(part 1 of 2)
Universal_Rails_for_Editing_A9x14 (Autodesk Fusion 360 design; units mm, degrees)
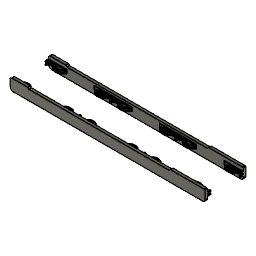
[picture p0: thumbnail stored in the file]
parameter "d466" = -2.1
extrude "Extrude1" new body blind 15
extrude "Extrude2" add blind 2
extrude "Extrude3" cut blind -100
extrude "Extrude4" cut blind -18
extrude "Extrude5" add of existing geometry blind 20
extrude "Extrude6" add of existing geometry blind 20
extrude "Extrude7" cut blind -30
extrude "Extrude8" cut of existing geometry blind -2.5
extrude "Extrude9" cut of existing geometry blind -2.5
extrude "Extrude10" cut of existing geometry blind -28
extrude "Extrude11" add of existing geometry blind 2
extrude "Extrude12" cut blind -21
extrude "Extrude13" cut blind -130
extrude "Extrude14" cut blind -14
extrude "Extrude15" cut blind -4
extrude "Extrude16" cut blind -9
extrude "Extrude17" cut blind -115
extrude "Extrude18" new body blind -2.75
extrude "Extrude19" new body blind -2.75
extrude "Extrude20" cut blind -2
extrude "Extrude21" new body blind -2
extrude "Extrude22" add of existing geometry blind 0.75
extrude "Extrude23" cut blind -9
extrude "Extrude24" cut blind -65
extrude "Extrude25" new body blind 1.5
extrude "Extrude26" cut blind -68
chamfer "Chamfer1" distance 1.5
chamfer "Chamfer2" distance 1.5
extrude "Extrude27" cut blind -0.5
extrude "Extrude28" add blind 1
chamfer "Chamfer3" distance 1
extrude "Extrude29" add of existing geometry blind 1
chamfer "Chamfer4" distance 1
extrude "Extrude30" cut of existing geometry blind -8
extrude "Extrude31" cut blind -2.75
extrude "Extrude32" cut blind -2.75
extrude "Extrude33" cut blind -2.75
extrude "Extrude34" cut blind -2.75
chamfer "Chamfer5" distance 3
chamfer "Chamfer6" distance 1
chamfer "Chamfer7" distance 1
chamfer "Chamfer8" distance 1
extrude "Extrude35" cut blind -0.1
extrude "Extrude36" cut blind -0.1
sketch "Sketch27" plane through (0, -1, 0) normal (0, -1, 0) x axis (1, 0, 0)
  line L1 (3, -2) -> (3, 15)
  line L2 (276.5, -2) -> (3, -2)
  line L3 (276.5, 15) -> (276.5, -2)
  line L4 (3, 15) -> (276.5, 15)
  line L5 (24, -1) -> (126, -1)
  line L6 (24, 14) -> (24, -1)
  line L7 (118, 14) -> (24, 14)
  line L8 (126, -1) -> (118, 14)
  line L9 (153, 10) -> (153, 15)
  line L10 (157.6985, 11.7101) -> (153, 10)
  line L11 (158, 10) -> (153, 10)
  line L12 (157.6985, 3.7101) -> (157.6985, 11.7101)
  line L13 (153, 5.4202) -> (157.6985, 3.7101)
  line L14 (162.6985, 3.7101) -> (157.6985, 3.7101)
  line L15 (153, -2) -> (153, 5.4202)
  circle C1 centre (198.75, 8) radius 1.25
  circle C2 centre (12, 8) radius 1.25
  point P12 (153, 15)
  point P19 (153, -2)
  point P13 (153, 10)
  point P14 (157.6985, 11.7101)
  point P16 (157.6985, 3.7101)
  point P17 (153, 5.4202)
  coincident L4 P12
  perpendicular L4 L9
  horizontal L11
  perpendicular L4 L12
  horizontal L14
  coincident L2 P19
  perpendicular L2 L15
  dimension "d170" distance P13 P14 = 5
  dimension "d171" angle L10 L11 = 20
  dimension "d172" distance P14 P16 = 8
  dimension "d173" angle L13 L14 = 160
  dimension "d174" distance P16 P17 = 5
sketch "Sketch28" plane through (0, 99, 0) normal (0, 1, 0) x axis (-1, 0, 0)
  line L1 (-3, 15) -> (-3, -2)
  line L2 (-25, 15) -> (-3, 15)
  line L3 (-26.7678, 13.2322) -> (-25, 15)
  line L4 (-226.7678, 13.2322) -> (-26.7678, 13.2322)
  line L5 (-228.5355, 15) -> (-226.7678, 13.2322)
  line L6 (-276.5, 15) -> (-228.5355, 15)
  line L7 (-276.5, 0) -> (-276.5, 15)
  line L8 (-276.5, -2) -> (-276.5, 0)
  line L9 (-3, -2) -> (-276.5, -2)
  line L10 (-126.1773, 9) -> (-126.1773, 13.2322)
  line L11 (-121.4789, 10.7101) -> (-126.1773, 9)
  line L12 (-121.1773, 9) -> (-126.1773, 9)
  line L13 (-121.4789, 2.7101) -> (-121.4789, 10.7101)
  line L14 (-126.1773, 4.4202) -> (-121.4789, 2.7101)
  line L15 (-116.4789, 2.7101) -> (-121.4789, 2.7101)
  line L16 (-126.1773, -2) -> (-126.1773, 4.4202)
  line L17 (-154.3022, -2) -> (-126.1773, -2)
  circle C1 centre (-245.5, 8) radius 1.25
  circle C2 centre (-12, 8) radius 1.25
  circle C3 centre (-138.5, 8) radius 1.25
  point P14 (-126.1773, 13.2322)
  point P21 (-126.1773, -2)
  point P15 (-126.1773, 9)
  point P16 (-121.4789, 10.7101)
  point P18 (-121.4789, 2.7101)
  point P19 (-126.1773, 4.4202)
  coincident L4 P14
  perpendicular L4 L10
  horizontal L12
  perpendicular L12 L13
  horizontal L15
  coincident L9 P21
  perpendicular L9 L16
  horizontal L17
  dimension "d175" angle L11 L12 = 20
  dimension "d176" distance P15 P16 = 5
  dimension "d177" distance P16 P18 = 8
  dimension "d178" angle L14 L15 = 160
  dimension "d179" distance P18 P19 = 5
sketch "Sketch31" plane through (0, 0, -2) normal (0, 0, -1) x axis (1, 0, 0)
  line L1 (172.6093, -76.3093) -> (197.4266, -76.3538)
  line L2 (208.9925, -86.3745) -> (161.1508, -86.2888)
  line L3 (153, -20) -> (153, 1)
  line L4 (126.2, -85) -> (126.2, -99)
  line L5 (153, -20) -> (126.2, -85)
  arc A1 centre (138.75, -49) radius 43.5 clockwise from (172.6093, -76.3093) to (161.1508, -86.2888)
  arc A2 centre (231.25, -49) radius 43.5 clockwise from (208.9925, -86.3745) to (197.4266, -76.3538)
  vertical L3
  vertical L4
copy_paste_bodies "CopyPasteBodies3"
move "Move3"
copy_paste_bodies "CopyPasteBodies4"
move "Move4"
extrude "Extrude38" cut sketch "Sketch27" profile of L2 L3 L4 C1 L9 L10 L12 L13 L15 against normal blind 60
extrude "Extrude39" cut of existing geometry blind -45
extrude "Extrude40" cut sketch "Sketch28" profile of L4 L5 L6 L7 L8 L9 C1 C3 L10 L11 L13 L14 L16 L17 against normal blind 50
extrude "Extrude41" cut of existing geometry blind -30
sketch "Sketch32" plane through (279, 0, 0) normal (1, 0, 0) x axis (0, 1, 0)
  line L1 (2.75, 15) -> (2.75, 0)
  line L2 (1.5, 15) -> (2.75, 15)
  line L3 (1.5, -1.9) -> (1.5, 15)
  line L4 (11.5, -1.9) -> (1.5, -1.9)
  line L5 (11.5, -2) -> (11.5, -1.9)
  line L6 (21.5, -2) -> (11.5, -2)
  line L7 (21.5, -1.9) -> (21.5, -2)
  line L8 (31.5, -1.9) -> (21.5, -1.9)
  line L9 (31.5, -2) -> (31.5, -1.9)
  line L10 (41.5001, -2) -> (31.5, -2)
  line L11 (41.5001, -1.9) -> (41.5001, -2)
  line L12 (56.4999, -1.9) -> (41.5001, -1.9)
  line L13 (56.4999, -2) -> (56.4999, -1.9)
  line L14 (66.5, -2) -> (56.4999, -2)
  line L15 (66.5, -1.9) -> (66.5, -2)
  line L16 (76.5, -1.9) -> (66.5, -1.9)
  line L17 (76.5, -2) -> (76.5, -1.9)
  line L18 (86.5, -2) -> (76.5, -2)
  line L19 (86.5, -1.9) -> (86.5, -2)
  line L20 (95.25, -1.9) -> (86.5, -1.9)
  line L21 (95.25, 0) -> (95.25, -1.9)
  line L22 (2.75, 0) -> (95.25, 0)
  line L23 (-12, -11) -> (105, -11)
  line L24 (-12, 30) -> (-12, -11)
  line L25 (105, 30) -> (-12, 30)
  line L26 (105, -11) -> (105, 30)
  horizontal L23
  vertical L24
  horizontal L25
  vertical L26
extrude "Extrude42" cut sketch "Sketch32" against normal blind 16
extrude "Extrude43" cut of existing geometry blind -10
extrude "Extrude44" cut sketch "Sketch27" profile of L1 L2 L4 C2 L5 L6 L7 L8 L9 L10 L12 L13 L15 against normal blind 45
extrude "Extrude45" cut sketch "Sketch28" profile of L1 L2 L3 L4 L9 C2 L10 L11 L13 L14 L16 against normal blind 51
extrude "Extrude46" cut of existing geometry blind -35
extrude "Extrude47" cut of existing geometry blind -20
extrude "Extrude48" cut of existing geometry blind -35
extrude "Extrude50" cut of existing geometry blind -15
extrude "Extrude51" cut of existing geometry blind -25
extrude "Extrude52" cut of existing geometry blind -0.3
extrude "Extrude53" cut of existing geometry blind -45
extrude "Extrude54" cut of existing geometry blind 29
extrude "Extrude55" cut of existing geometry blind -0.4
extrude "Extrude56" cut of existing geometry blind -2
extrude "Extrude57" cut of existing geometry blind -2
extrude "Extrude58" cut of existing geometry blind -2
extrude "Extrude77" add of existing geometry blind 0.5
extrude "Extrude78" add of existing geometry blind 0.5
fillet "Fillet21" radius 5.5
fillet "Fillet22" radius 1.75
extrude "Extrude79" add of existing geometry blind 0.1
extrude "Extrude80" add of existing geometry blind 0.1
extrude "Extrude81" add of existing geometry blind 0.1
extrude "Extrude82" add of existing geometry blind 0.1
extrude "Extrude83" cut of existing geometry blind -25
delete_face "DeleteFace1"
delete_face "DeleteFace2"
delete_face "DeleteFace3"
delete_face "DeleteFace4"
delete_face "DeleteFace5"
delete_face "DeleteFace6"
delete_face "DeleteFace7"
delete_face "DeleteFace8"
sketch "Sketch35" plane through (0, 97.25, 0) normal (0, -1, 0) x axis (1, 0, 0)
  line L1 (26.7678, 13.2322) -> (132.5, 13.2322)
  line L2 (25, 15) -> (26.7678, 13.2322)
  line L3 (18, 15) -> (25, 15)
  line L4 (18, 0) -> (18, 15)
  line L5 (132.5, 0) -> (18, 0)
  line L6 (132.5, 13.2322) -> (132.5, 0)
extrude "Extrude84" add of existing geometry blind 2.2
extrude "Extrude85" cut of existing geometry blind -2.2
extrude "Extrude86" add of existing geometry blind 108
delete_face "DeleteFace9"
delete_face "DeleteFace10"
delete_face "DeleteFace11"
delete_face "DeleteFace12"
delete_face "DeleteFace13"
delete_face "DeleteFace14"
delete_face "DeleteFace15"
delete_face "DeleteFace16"
delete_face "DeleteFace17"
delete_face "DeleteFace18"
delete_face "DeleteFace19"
copy_paste_bodies "CopyPasteBodies5"
move "Move7"
extrude "Extrude87" add of existing geometry blind 0.3
sketch "Sketch36" plane through (0, -1, 0) normal (0, -1, 0) x axis (1, 0, 0)
  line L1 (0, 15) -> (279, 15)
  line L2 (0, -2) -> (0, 15)
  line L3 (279, -2) -> (0, -2)
  line L4 (279, 15) -> (279, -2)
  line L5 (0, 15) -> (279, 15)
  line L6 (0, 10.3) -> (279, 10.3)
  circle C1 centre (198.75, 8) radius 1.25
  circle C2 centre (12, 8) radius 1.25
  point P2 (279, 15)
  point P8 (279, 15)
  point P3 (0, 15)
  point P9 (0, 15)
  coincident P2 P8
  coincident P3 P9
  dimension "d330" = -4.7
move "Move9"
move "Move10"
move "Move11"
copy_paste_bodies "CopyPasteBodies6"
move "Move12"
move "Move13"
extrude "Extrude88" cut of existing geometry blind 12 bodies "(1) (1) (1) (1)", "(1) (1) (1) (2)"
extrude "Extrude89" cut of existing geometry blind -8.5
extrude "Extrude90" cut of existing geometry blind -1
fillet "Fillet23" radius 0.2
fillet "Fillet24" radius 0.05
fillet "Fillet25" radius 0.05
move "Move14"
copy_paste_bodies "CopyPasteBodies7"
move "Move15"
move "Move16"
copy_paste_bodies "CopyPasteBodies8"
move "Move17"
copy_paste_bodies "CopyPasteBodies9"
move "Move18"
move "Move19"
move "Move20"
move "Move21"
move "Move22"
extrude "Extrude91" add sketch "Sketch35" along normal blind 1.95 bodies "(1) (1) (2)", "(1) (1) (1)"
extrude "Extrude92" add of existing geometry blind 1.95
copy_paste_bodies "CopyPasteBodies10"
move "Move23"
move "Move24"
move "Move25"
extrude "Extrude93" cut of existing geometry blind 8 bodies "(1) (1) (1) (3) (1) (1) (1)"
extrude "Extrude94" cut of existing geometry blind -2
sketch "Sketch37" plane through (0, 0, -2) normal (0, 0, -1) x axis (1, 0, 0)
  line L1 (252, -95.25) -> (277.5, -95.25)
  line L2 (252, -95.25) -> (252, -95.25)
  line L3 (277.5, -95.25) -> (252, -95.25)
  line L4 (252, -98) -> (260, -98)
  line L5 (252, -98) -> (252, -98)
  line L6 (260, -98) -> (252, -98)
  line L7 (0, 1) -> (279, 1)
  line L8 (0, -101.7) -> (0, 1)
  line L9 (279, -101.7) -> (0, -101.7)
  line L10 (279, 1) -> (279, -101.7)
  line L11 (279, -113.4909) -> (334.0073, -113.4909)
  line L12 (279, 5) -> (279, -113.4909)
  line L13 (334.0073, 5) -> (279, 5)
  line L14 (334.0073, -113.4909) -> (334.0073, 5)
  circle C1 centre (190.0257, -90.2243) radius 2
  circle C2 centre (190.0257, -7.7757) radius 2
  circle C3 centre (4.9009, -90.0991) radius 2
  circle C4 centre (97.5257, -90.2243) radius 2
  circle C5 centre (87.4743, -7.7757) radius 2
  circle C6 centre (46.25, -49) radius 43.5
  circle C7 centre (272.4743, -90.2243) radius 3
  circle C8 centre (138.75, -49) radius 43.5
  circle C9 centre (231.25, -49) radius 43.5
  circle C10 centre (97.5257, -7.7757) radius 2
  circle C11 centre (87.4743, -90.2243) radius 2
  circle C12 centre (5.0257, -7.7757) radius 2
  circle C13 centre (272.4743, -7.7757) radius 2
  circle C14 centre (179.9743, -7.7757) radius 2
  circle C15 centre (179.9743, -90.2243) radius 2
  horizontal L11
  vertical L12
  horizontal L13
  vertical L14
extrude "Extrude95" cut sketch "Sketch37" profile of L10 L11 L12 L13 L14 against normal blind 25
copy_paste_bodies "CopyPasteBodies11"
move "Move26"
move "Move27"
move "Move28"
move "Move29"
move "Move30"
sketch "Sketch38" plane through (0, 0, -2) normal (0, 0, -1) x axis (1, 0, 0)
  line L1 (252, -95.25) -> (277.5, -95.25)
  line L2 (252, -95.25) -> (252, -95.25)
  line L3 (277.5, -95.25) -> (252, -95.25)
  line L4 (252, -98) -> (260, -98)
  line L5 (252, -98) -> (252, -98)
  line L6 (260, -98) -> (252, -98)
  line L7 (0, 1) -> (279, 1)
  line L8 (0, -101.7) -> (0, 1)
  line L9 (279, -101.7) -> (0, -101.7)
  line L10 (279, 1) -> (279, -101.7)
  line L11 (0, -117.1495) -> (-75.3849, -117.1495)
  line L12 (0, 1) -> (0, -117.1495)
  line L13 (-75.3849, 1) -> (0, 1)
  line L14 (-75.3849, -117.1495) -> (-75.3849, 1)
  circle C1 centre (190.0257, -90.2243) radius 2
  circle C2 centre (190.0257, -7.7757) radius 2
  circle C3 centre (4.9009, -90.0991) radius 2
  circle C4 centre (97.5257, -90.2243) radius 2
  circle C5 centre (87.4743, -7.7757) radius 2
  circle C6 centre (46.25, -49) radius 43.5
  circle C7 centre (272.4743, -90.2243) radius 3
  circle C8 centre (138.75, -49) radius 43.5
  circle C9 centre (231.25, -49) radius 43.5
  circle C10 centre (97.5257, -7.7757) radius 2
  circle C11 centre (87.4743, -90.2243) radius 2
  circle C12 centre (5.0257, -7.7757) radius 2
  circle C13 centre (272.4743, -7.7757) radius 2
  circle C14 centre (179.9743, -7.7757) radius 2
  circle C15 centre (179.9743, -90.2243) radius 2
  point P19 (0, 1)
  point P30 (0, 1)
  horizontal L11
  vertical L12
  horizontal L13
  vertical L14
  coincident P19 P30
extrude "Extrude96" cut sketch "Sketch38" profile of L8 L11 L12 L13 L14 against normal blind 60
extrude "Extrude97" cut of existing geometry blind 11 bodies "(1) (1) (1) (3) (3)", "(1) (1) (1) (3) (4)"
extrude "Extrude98" cut of existing geometry blind -8.5
extrude "Extrude99" cut of existing geometry blind -1.5
extrude "Extrude100" cut of existing geometry blind 15 bodies "(1) (1) (1) (3) (2) (1)", "Side 1"
extrude "Extrude101" cut of existing geometry blind -8.5
extrude "Extrude102" cut of existing geometry blind -50 bodies "Part 1 (1)"
sketch "Sketch39" plane through (0, 0, 15) normal (0, 0, 1) x axis (-1, 0, 0)
  line L1 (-279, 1) -> (0, 1)
  line L2 (-279, -3.05) -> (-279, 1)
  line L3 (-204.75, -3.05) -> (-279, -3.05)
  line L4 (-204.75, 0) -> (-204.75, -3.05)
  line L5 (-192.75, 0) -> (-204.75, 0)
  line L6 (-192.75, -3.05) -> (-192.75, 0)
  line L7 (-18, -3.05) -> (-192.75, -3.05)
  line L8 (-18, 0) -> (-18, -3.05)
  line L9 (-6, 0) -> (-18, 0)
  line L10 (-6, -3.05) -> (-6, 0)
  line L11 (0, -3.05) -> (-6, -3.05)
  line L12 (0, 1) -> (0, -3.05)
  line L13 (-278.8, -3.05) -> (-279, -3.05)
  line L14 (-279, -3.05) -> (0, -3.05)
  line L15 (-279, -1.05) -> (0, -1.05)
  line L16 (-278.8, -5.05) -> (-279, -5.05)
  arc A1 centre (-279, -3.05) radius 2 clockwise from (-279, -5.05) to (-279, -1.05)
  point P4 (-279, -3.05)
  point P14 (-279, -3.05)
  point P15 (-278.8, -3.05)
  point P13 (0, -3.05)
  point P16 (0, -3.05)
  coincident P4 P14
  coincident L3 P15
  coincident P13 P16
  dimension "d367" = 2
extrude "Extrude103" cut sketch "Sketch39" profile of L2 L3 L4 L6 L7 L8 L10 L11 L12 L13 L14 L15 against normal blind 3
fillet "Fillet26" radius 1.5
fillet "Fillet27" radius 1.5
extrude "Extrude104" cut of existing geometry blind -1
extrude "Extrude105" cut of existing geometry blind -1
fillet "Fillet28" radius 5
delete_face "DeleteFace20"
delete_face "DeleteFace21"
delete_face "DeleteFace22"
extrude "Extrude106" cut of existing geometry blind -1
extrude "Extrude107" cut of existing geometry blind -1
fillet "Fillet29" radius 1.25
fillet "Fillet30" radius 2
fillet "Fillet31" radius 2.5
combine "Combine1" bodies "Part 1 (1)"
combine "Combine2" bodies "(1) (1) (1) (3) (1) (1) (1) (1)", "(1) (1) (1) (3) (2) (1)"
combine "Combine3" bodies "(1) (1) (1) (3) (1) (1) (1) (1)", "(1) (1) (1) (3) (1) (1) (1)"
combine "Combine4" bodies "(1) (1) (1) (3) (4) (1)", "(1) (1) (1) (3) (4) (2)", "(1) (1) (1) (3) (4) (3)", "(1) (1) (1) (3) (4) (4)", "(1) (1) (1) (3) (4) (5)", "(1) (1) (1) (3) (3)", "(1) (1) (1) (3) (1)", "(1) (1) (1) (3)"
combine "Combine5" bodies "(1) (1) (1) (3) (4) (3)", "(1) (1) (1) (3) (4) (5)", "(1) (1) (1) (3) (4) (1)", "(1) (1) (1) (3) (4) (4)"
extrude "Extrude108" add of existing geometry blind 2.5 bodies "(1) (1) (1) (3) (4)", "(1) (1) (1) (3) (2)"
extrude "Extrude109" add of existing geometry blind 2.5
extrude "Extrude110" add of existing geometry blind 2.5
extrude "Extrude111" add of existing geometry blind 2.5
extrude "Extrude112" cut of existing geometry blind -2.5
delete_face "DeleteFace23"
delete_face "DeleteFace24"
delete_face "DeleteFace25"
extrude "Extrude113" cut of existing geometry blind -2.5
extrude "Extrude114" cut of existing geometry blind -3
extrude "Extrude115" cut of existing geometry blind -3
extrude "Extrude116" cut of existing geometry blind -0.5
extrude "Extrude117" cut of existing geometry blind -0.5
fillet "Fillet32" radius 2
extrude "Extrude118" add of existing geometry blind 2
fillet "Fillet33" radius 2
sketch "Sketch40" plane through (0, -2.5, 0) normal (0, 1, 0) x axis (-1, 0, 0)
  line L1 (-192.75, -1) -> (-204.75, -1)
  line L2 (-192.75, 15) -> (-192.75, -1)
  line L3 (-204.75, 15) -> (-192.75, 15)
  line L4 (-204.75, -1) -> (-204.75, 15)
  line L5 (-192.75, -1) -> (-204.75, -1)
  line L6 (-192.75, 0) -> (-204.75, 0)
  circle C1 centre (-198.75, 8) radius 1.25
  point P2 (-204.75, -1)
  point P7 (-204.75, -1)
  point P3 (-192.75, -1)
  point P8 (-192.75, -1)
  coincident P2 P7
  coincident P3 P8
  dimension "d416" distance ORIGIN L5 = -1
extrude "Extrude119" new body sketch "Sketch40" profile of L1 L2 L4 L5 L6 along normal blind 5.55
sketch "Sketch41" plane through (0, -2.5, 0) normal (0, 1, 0) x axis (-1, 0, 0)
  line L1 (-6, -1) -> (-18, -1)
  line L2 (-6, 15) -> (-6, -1)
  line L3 (-18, 15) -> (-6, 15)
  line L4 (-18, -1) -> (-18, 15)
  line L5 (-6, -1) -> (-18, -1)
  line L6 (-6, 0) -> (-18, 0)
  circle C1 centre (-12, 8) radius 1.25
  point P2 (-18, -1)
  point P7 (-18, -1)
  point P3 (-6, -1)
  point P8 (-6, -1)
  coincident P2 P7
  coincident P3 P8
  dimension "d419" distance ORIGIN L5 = -1
extrude "Extrude120" new body sketch "Sketch41" profile of L1 L2 L4 L5 L6 along normal blind 5.55
combine "Combine6" bodies "(1) (1) (1) (3) (4) (2)"
base_mesh_feature "Base Mesh Feature3"
modify "Modify1"
modify "Modify2"
modify "Modify3"
modify "Modify4"
convert_mesh "Convert Mesh" bodies "(1)"
combine "Combine7" bodies "Side 1"
extrude "Extrude121" add of existing geometry blind 1
extrude "Extrude122" add of existing geometry blind 1
fillet "Fillet34" radius 1.5
fillet "Fillet35" radius 1.5
sketch "Sketch42" plane through (0, 97.7, 0) normal (0, -1, 0) x axis (1, 0, 0)
  line L1 (251.5, -1) -> (239.5, -1)
  line L2 (251.5, 15) -> (251.5, -1)
  line L3 (239.5, 15) -> (251.5, 15)
  line L4 (239.5, -1) -> (239.5, 15)
  line L5 (18, -1) -> (6, -1)
  line L6 (132.5, -1) -> (18, -1)
  line L7 (144.5, -1) -> (132.5, -1)
  line L8 (18, 0) -> (6, 0)
  line L9 (132.5, 0) -> (18, 0)
  line L10 (144.5, 0) -> (132.5, 0)
  line L11 (18, -1) -> (18, 0)
  line L12 (144.5, 0) -> (144.5, -1)
  line L13 (132.5, -1) -> (132.5, 0)
  line L14 (6, -0.1) -> (6, 0)
  line L15 (6, -1) -> (6, -0.1)
  circle C1 centre (245.5, 8) radius 1.25
  horizontal L5
  parallel L5 L6
  parallel L6 L7
  perpendicular L6 L11
  perpendicular L10 L12
  perpendicular L6 L13
  perpendicular L8 L14
  perpendicular L5 L15
  dimension "d430" distance ORIGIN L7 = -1
extrude "Extrude123" new body sketch "Sketch42" profile of L5 L7 L8 L10 L11 L12 L13 L14 L15 along normal blind 2.4
combine "Combine8" bodies "(1)"
extrude "Extrude124" add of existing geometry blind 1
fillet "Fillet36" radius 1.5
fillet "Fillet37" radius 1.5
sketch "Sketch43" plane through (0, 97.7, 0) normal (0, -1, 0) x axis (1, 0, 0)
  line L1 (251.5, -1) -> (239.5, -1)
  line L2 (251.5, 15) -> (251.5, -1)
  line L3 (239.5, 15) -> (251.5, 15)
  line L4 (239.5, -1) -> (239.5, 15)
  line L5 (239.5, -1) -> (251.5, -1)
  line L6 (239.5, 1.5) -> (251.5, 1.5)
  circle C1 centre (245.5, 8) radius 1.25
  point P3 (251.5, -1)
  point P7 (251.5, -1)
  point P2 (239.5, -1)
  point P8 (239.5, -1)
  coincident P3 P7
  coincident P2 P8
  dimension "d439" = 2.5
extrude "Extrude125" new body sketch "Sketch43" profile of L1 L2 L4 L5 L6 along normal blind 2.45
combine "Combine9"
fillet "Fillet38" radius 1.5
extrude "Extrude126" cut of existing geometry blind -0.05
extrude "Extrude127" add of existing geometry blind 0.5
chamfer "Chamfer9" distance 0.5
chamfer "Chamfer10" distance 0.5
chamfer "Chamfer11" distance 0.5
chamfer "Chamfer12" distance 0.5
fillet "Fillet39" radius 0.5
fillet "Fillet40" radius 0.5
fillet "Fillet41" radius 0.25
delete_face "DeleteFace26"
extrude "Extrude128" cut of existing geometry blind -43
fillet "Fillet42" radius 1.5
delete_face "DeleteFace27"
extrude "Extrude129" cut of existing geometry blind -0.55
extrude "Extrude130" cut of existing geometry blind -0.2
extrude "Extrude131" cut of existing geometry no distance stored
fillet "Fillet43" radius 1
sketch "Sketch44" plane through (0, -4, 0) normal (0, -1, 0) x axis (1, 0, 0)
  line L1 (2, 15) -> (203.25, 15)
  line L2 (0, 4) -> (0, 13)
  line L3 (274, -1) -> (5, -1)
  line L4 (279, 10.5) -> (279, 4)
  line L5 (206.25, 10.5) -> (279, 10.5)
  line L6 (204.75, 13.5) -> (204.75, 12)
  line L7 (12, 9) -> (12, 8)
  arc A1 centre (203.25, 13.5) radius 1.5 clockwise from (203.25, 15) to (204.75, 13.5)
  arc A2 centre (2, 13) radius 2 clockwise from (0, 13) to (2, 15)
  arc A3 centre (5, 4) radius 5 clockwise from (5, -1) to (0, 4)
  arc A4 centre (274, 4) radius 5 clockwise from (279, 4) to (274, -1)
  arc A5 centre (206.25, 12) radius 1.5 clockwise from (206.25, 10.5) to (204.75, 12)
  circle C1 centre (198.75, 8) radius 1.75
  circle C2 centre (12, 8) radius 1.75
  circle C3 centre (12, 9) radius 1
  point P19 (12, 8)
  point P20 (12, 8)
  point P21 (12, 9)
  point P22 (12, 9)
  coincident P19 P20
  vertical L7
  coincident P21 P22
  dimension "d471" distance P20 P21 = 1
  dimension "d472" diameter C3 = 2
extrude "Extrude132" new body sketch "Sketch44" profile of C2 C3 along normal blind 1
delete_face "DeleteFace28"
delete_face "DeleteFace29"
extrude "Extrude133" cut of existing geometry blind -18
chamfer "Chamfer13" distance 0.75
sketch "Sketch45" plane through (0, -4, 0) normal (0, -1, 0) x axis (1, 0, 0)
  line L1 (2, 15) -> (203.25, 15)
  line L2 (0, 4) -> (0, 13)
  line L3 (274, -1) -> (5, -1)
  line L4 (279, 10.5) -> (279, 4)
  line L5 (206.25, 10.5) -> (279, 10.5)
  line L6 (204.75, 13.5) -> (204.75, 12)
  line L7 (198.75, 9) -> (198.75, 8)
  arc A1 centre (203.25, 13.5) radius 1.5 clockwise from (203.25, 15) to (204.75, 13.5)
  arc A2 centre (2, 13) radius 2 clockwise from (0, 13) to (2, 15)
  arc A3 centre (5, 4) radius 5 clockwise from (5, -1) to (0, 4)
  arc A4 centre (274, 4) radius 5 clockwise from (279, 4) to (274, -1)
  arc A5 centre (206.25, 12) radius 1.5 clockwise from (206.25, 10.5) to (204.75, 12)
  circle C1 centre (198.75, 8) radius 1.75
  circle C2 centre (12, 9) radius 1.75
  circle C3 centre (198.75, 8) radius 1
  circle C4 centre (198.75, 9) radius 1
  point P20 (198.75, 8)
  point P21 (198.75, 8)
  point P22 (198.75, 9)
  point P23 (198.75, 9)
  concentric C1 C3
  coincident P20 P21
  coincident C3 P22
  vertical L7
  coincident P22 P23
  dimension "d478" diameter C3 = 2
  dimension "d479" diameter C4 = 2
extrude "Extrude134" add sketch "Sketch45" profile of C1 C3 L7 C4 along normal blind 2.4
delete_face "DeleteFace30"
delete_face "DeleteFace31"
extrude "Extrude135" cut of existing geometry blind -14
chamfer "Chamfer14" distance 0.75
sketch "Sketch46" plane through (0, 3.05, 0) normal (0, 1, 0) x axis (-1, 0, 0)
  line L1 (-158.6084, 10) -> (-118.9527, 10)
  line L2 (-158.6088, 8.7626) -> (-158.6084, 10)
  line L3 (-158.6088, 8.5) -> (-158.6088, 8.7626)
  line L4 (-158.9877, 8.5) -> (-158.6088, 8.5)
  line L5 (-159.0663, 8.5) -> (-158.9877, 8.5)
  line L6 (-185.3992, 8.5) -> (-159.0663, 8.5)
  line L7 (-185.4405, 8.5) -> (-185.3992, 8.5)
  line L8 (-185.4826, 8.5) -> (-185.4405, 8.5)
  line L9 (-185.506, 8.5) -> (-185.4826, 8.5)
  line L10 (-185.5175, 8.5) -> (-185.506, 8.5)
  line L11 (-185.5304, 8.5) -> (-185.5175, 8.5)
  line L12 (-185.5304, 8.5056) -> (-185.5304, 8.5)
  line L13 (-185.5304, 10) -> (-185.5304, 8.5056)
  line L14 (-185.5307, 10) -> (-185.5304, 10)
  line L15 (-185.5307, 8.5056) -> (-185.5307, 10)
  line L16 (-185.5307, 8.5) -> (-185.5307, 8.5056)
  line L17 (-185.5342, 8.5) -> (-185.5307, 8.5)
  line L18 (-185.5382, 8.5) -> (-185.5342, 8.5)
  line L19 (-185.547, 8.5) -> (-185.5382, 8.5)
  line L20 (-185.5661, 8.5) -> (-185.547, 8.5)
  line L21 (-185.6018, 8.5) -> (-185.5661, 8.5)
  line L22 (-185.6391, 8.5) -> (-185.6018, 8.5)
  line L23 (-192.75, 8.5) -> (-185.6391, 8.5)
  line L24 (-192.75, 6.5) -> (-192.75, 8.5)
  line L25 (-185.6391, 6.5) -> (-192.75, 6.5)
  line L26 (-185.6018, 6.5) -> (-185.6391, 6.5)
  line L27 (-185.5661, 6.5) -> (-185.6018, 6.5)
  line L28 (-185.547, 6.5) -> (-185.5661, 6.5)
  line L29 (-185.5382, 6.5) -> (-185.547, 6.5)
  line L30 (-185.5342, 6.5) -> (-185.5382, 6.5)
  line L31 (-185.5324, 6.5) -> (-185.5342, 6.5)
  line L32 (-185.5323, 6.5) -> (-185.5324, 6.5)
  line L33 (-185.5321, 6.5) -> (-185.5323, 6.5)
  line L34 (-185.5318, 6.5) -> (-185.5321, 6.5)
  line L35 (-185.5316, 6.5) -> (-185.5318, 6.5)
  line L36 (-185.5314, 6.5) -> (-185.5316, 6.5)
  line L37 (-185.5311, 6.5) -> (-185.5314, 6.5)
  line L38 (-185.5307, 6.5) -> (-185.5311, 6.5)
  line L39 (-185.5307, 4.7056) -> (-185.5307, 6.5)
  line L40 (-185.5307, 4.7) -> (-185.5307, 4.7056)
  line L41 (-185.5311, 4.7) -> (-185.5307, 4.7)
  line L42 (-185.5743, 4.7) -> (-185.5311, 4.7)
  line L43 (-185.6006, 4.7) -> (-185.5743, 4.7)
  line L44 (-185.6265, 4.7) -> (-185.6006, 4.7)
  line L45 (-185.6513, 4.7) -> (-185.6265, 4.7)
  line L46 (-185.6745, 4.7) -> (-185.6513, 4.7)
  line L47 (-185.6956, 4.7) -> (-185.6745, 4.7)
  line L48 (-185.8704, 4.7) -> (-185.6956, 4.7)
  line L49 (-186.1657, 4.7) -> (-185.8704, 4.7)
  line L50 (-186.6749, 4.7) -> (-186.1657, 4.7)
  line L51 (-187.4335, 4.7) -> (-186.6749, 4.7)
  line L52 (-188.3776, 4.7) -> (-187.4335, 4.7)
  line L53 (-189.2796, 4.7) -> (-188.3776, 4.7)
  line L54 (-192.75, 4.7) -> (-189.2796, 4.7)
  line L55 (-192.75, 2.5) -> (-192.75, 4.7)
  line L56 (-203.25, 1) -> (-194.25, 1)
  line L57 (-204.75, 4.7) -> (-204.75, 2.5)
  line L58 (-207.5504, 4.7) -> (-204.75, 4.7)
  line L59 (-208.7719, 4.7) -> (-207.5504, 4.7)
  line L60 (-209.2062, 4.7) -> (-208.7719, 4.7)
  line L61 (-211.0064, 4.7) -> (-209.2062, 4.7)
  line L62 (-211.4528, 4.7) -> (-211.0064, 4.7)
  line L63 (-211.4523, 6.2374) -> (-211.4528, 4.7)
  line L64 (-211.4524, 6.5) -> (-211.4523, 6.2374)
  line L65 (-211.0734, 6.5) -> (-211.4524, 6.5)
  line L66 (-210.9948, 6.5) -> (-211.0734, 6.5)
  line L67 (-204.75, 6.5) -> (-210.9948, 6.5)
  line L68 (-204.75, 8.5) -> (-204.75, 6.5)
  line L69 (-210.9948, 8.5) -> (-204.75, 8.5)
  line L70 (-211.0734, 8.5) -> (-210.9948, 8.5)
  line L71 (-211.4524, 8.5) -> (-211.0734, 8.5)
  line L72 (-211.4523, 8.7626) -> (-211.4524, 8.5)
  line L73 (-211.4527, 10) -> (-211.4523, 8.7626)
  line L74 (-251.1084, 10) -> (-211.4527, 10)
  line L75 (-251.1088, 8.7626) -> (-251.1084, 10)
  line L76 (-251.1088, 8.5) -> (-251.1088, 8.7626)
  line L77 (-251.4877, 8.5) -> (-251.1088, 8.5)
  line L78 (-251.5663, 8.5) -> (-251.4877, 8.5)
  line L79 (-277.8992, 8.5) -> (-251.5663, 8.5)
  line L80 (-277.9405, 8.5) -> (-277.8992, 8.5)
  line L81 (-277.9826, 8.5) -> (-277.9405, 8.5)
  line L82 (-278.006, 8.5) -> (-277.9826, 8.5)
  line L83 (-278.0175, 8.5) -> (-278.006, 8.5)
  line L84 (-278.0304, 8.5) -> (-278.0175, 8.5)
  line L85 (-278.0304, 8.5056) -> (-278.0304, 8.5)
  line L86 (-278.0304, 10) -> (-278.0304, 8.5056)
  line L87 (-278.0307, 10) -> (-278.0304, 10)
  line L88 (-278.0307, 8.5056) -> (-278.0307, 10)
  line L89 (-278.0307, 8.5) -> (-278.0307, 8.5056)
  line L90 (-278.0342, 8.5) -> (-278.0307, 8.5)
  line L91 (-278.0382, 8.5) -> (-278.0342, 8.5)
  line L92 (-278.047, 8.5) -> (-278.0382, 8.5)
  line L93 (-278.0661, 8.5) -> (-278.047, 8.5)
  line L94 (-278.1018, 8.5) -> (-278.0661, 8.5)
  line L95 (-278.1391, 8.5) -> (-278.1018, 8.5)
  line L96 (-279, 8.5) -> (-278.1391, 8.5)
  line L97 (-279, 6.5) -> (-279, 8.5)
  line L98 (-278.1391, 6.5) -> (-279, 6.5)
  line L99 (-278.1018, 6.5) -> (-278.1391, 6.5)
  line L100 (-278.0661, 6.5) -> (-278.1018, 6.5)
  line L101 (-278.047, 6.5) -> (-278.0661, 6.5)
  line L102 (-278.0382, 6.5) -> (-278.047, 6.5)
  line L103 (-278.0342, 6.5) -> (-278.0382, 6.5)
  line L104 (-278.0324, 6.5) -> (-278.0342, 6.5)
  line L105 (-278.0323, 6.5) -> (-278.0324, 6.5)
  line L106 (-278.0321, 6.5) -> (-278.0323, 6.5)
  line L107 (-278.0318, 6.5) -> (-278.0321, 6.5)
  line L108 (-278.0316, 6.5) -> (-278.0318, 6.5)
  line L109 (-278.0314, 6.5) -> (-278.0316, 6.5)
  line L110 (-278.0311, 6.5) -> (-278.0314, 6.5)
  line L111 (-278.0307, 6.5) -> (-278.0311, 6.5)
  line L112 (-278.0307, 4.7056) -> (-278.0307, 6.5)
  line L113 (-278.0307, 4.7) -> (-278.0307, 4.7056)
  line L114 (-278.0311, 4.7) -> (-278.0307, 4.7)
  line L115 (-278.0743, 4.7) -> (-278.0311, 4.7)
  line L116 (-278.1006, 4.7) -> (-278.0743, 4.7)
  line L117 (-278.1265, 4.7) -> (-278.1006, 4.7)
  line L118 (-278.1513, 4.7) -> (-278.1265, 4.7)
  line L119 (-278.1745, 4.7) -> (-278.1513, 4.7)
  line L120 (-278.1956, 4.7) -> (-278.1745, 4.7)
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  point P385 (-61.3466, 10)
  point P386 (-31.3466, 10)
  point P388 (-61.3466, 4)
  dimension "d485" distance P385 P386 = 30
  dimension "d486" distance P385 P388 = 6
extrude "Extrude136" cut sketch "Sketch46" against normal blind 5.55
extrude "Extrude137" cut of existing geometry blind -6
fillet "Fillet44" radius 3.5
sketch "Sketch47" plane through (0, 3.05, 0) normal (0, 1, 0) x axis (-1, 0, 0)
  line L1 (-185.5175, 6.5) -> (-185.5304, 6.5)
  line L2 (-185.506, 6.5) -> (-185.5175, 6.5)
  line L3 (-185.4826, 6.5) -> (-185.506, 6.5)
  line L4 (-185.4405, 6.5) -> (-185.4826, 6.5)
  line L5 (-185.3992, 6.5) -> (-185.4405, 6.5)
  line L6 (-159.0663, 6.5) -> (-185.3992, 6.5)
  line L7 (-158.9877, 6.5) -> (-159.0663, 6.5)
  line L8 (-158.6088, 6.5) -> (-158.9877, 6.5)
  line L9 (-158.6088, 6.2374) -> (-158.6088, 6.5)
  line L10 (-158.6083, 4.7) -> (-158.6088, 6.2374)
  line L11 (-159.0547, 4.7) -> (-158.6083, 4.7)
  line L12 (-160.8549, 4.7) -> (-159.0547, 4.7)
  line L13 (-161.2892, 4.7) -> (-160.8549, 4.7)
  line L14 (-162.5107, 4.7) -> (-161.2892, 4.7)
  line L15 (-180.9918, 4.7) -> (-162.5107, 4.7)
  line L16 (-185.3987, 4.7) -> (-180.9918, 4.7)
  line L17 (-185.4402, 4.7) -> (-185.3987, 4.7)
  line L18 (-185.4824, 4.7) -> (-185.4402, 4.7)
  line L19 (-185.506, 4.7) -> (-185.4824, 4.7)
  line L20 (-185.5174, 4.7) -> (-185.506, 4.7)
  line L21 (-185.5229, 4.7) -> (-185.5174, 4.7)
  line L22 (-185.5272, 4.7) -> (-185.5229, 4.7)
  line L23 (-185.5304, 4.7) -> (-185.5272, 4.7)
  line L24 (-185.5304, 6.4944) -> (-185.5304, 4.7)
  line L25 (-185.5304, 6.5) -> (-185.5304, 6.4944)
  line L26 (-118.5734, 6.5) -> (-118.9524, 6.5)
  line L27 (-118.4948, 6.5) -> (-118.5734, 6.5)
  line L28 (-93.1391, 6.5) -> (-118.4948, 6.5)
  line L29 (-93.1018, 6.5) -> (-93.1391, 6.5)
  line L30 (-93.0661, 6.5) -> (-93.1018, 6.5)
  line L31 (-93.047, 6.5) -> (-93.0661, 6.5)
  line L32 (-93.0382, 6.5) -> (-93.047, 6.5)
  line L33 (-93.0342, 6.5) -> (-93.0382, 6.5)
  line L34 (-93.0324, 6.5) -> (-93.0342, 6.5)
  line L35 (-93.0323, 6.5) -> (-93.0324, 6.5)
  line L36 (-93.0321, 6.5) -> (-93.0323, 6.5)
  line L37 (-93.0318, 6.5) -> (-93.0321, 6.5)
  line L38 (-93.0316, 6.5) -> (-93.0318, 6.5)
  line L39 (-93.0314, 6.5) -> (-93.0316, 6.5)
  line L40 (-93.0311, 6.5) -> (-93.0314, 6.5)
  line L41 (-93.0307, 6.5) -> (-93.0311, 6.5)
  line L42 (-93.0307, 4.7056) -> (-93.0307, 6.5)
  line L43 (-93.0307, 4.7) -> (-93.0307, 4.7056)
  line L44 (-93.0311, 4.7) -> (-93.0307, 4.7)
  line L45 (-93.0743, 4.7) -> (-93.0311, 4.7)
  line L46 (-93.1006, 4.7) -> (-93.0743, 4.7)
  line L47 (-93.1265, 4.7) -> (-93.1006, 4.7)
  line L48 (-93.1513, 4.7) -> (-93.1265, 4.7)
  line L49 (-93.1745, 4.7) -> (-93.1513, 4.7)
  line L50 (-93.1956, 4.7) -> (-93.1745, 4.7)
  line L51 (-93.3704, 4.7) -> (-93.1956, 4.7)
  line L52 (-93.6657, 4.7) -> (-93.3704, 4.7)
  line L53 (-94.1749, 4.7) -> (-93.6657, 4.7)
  line L54 (-94.9335, 4.7) -> (-94.1749, 4.7)
  line L55 (-95.8776, 4.7) -> (-94.9335, 4.7)
  line L56 (-96.7796, 4.7) -> (-95.8776, 4.7)
  line L57 (-115.0504, 4.7) -> (-96.7796, 4.7)
  line L58 (-116.2719, 4.7) -> (-115.0504, 4.7)
  line L59 (-116.7062, 4.7) -> (-116.2719, 4.7)
  line L60 (-118.5064, 4.7) -> (-116.7062, 4.7)
  line L61 (-118.9528, 4.7) -> (-118.5064, 4.7)
  line L62 (-118.9523, 6.2374) -> (-118.9528, 4.7)
  line L63 (-118.9524, 6.5) -> (-118.9523, 6.2374)
  line L64 (-66.1083, 4.7) -> (-66.1088, 6.2374)
  line L65 (-66.5547, 4.7) -> (-66.1083, 4.7)
  line L66 (-68.3549, 4.7) -> (-66.5547, 4.7)
  line L67 (-68.7892, 4.7) -> (-68.3549, 4.7)
  line L68 (-70.0107, 4.7) -> (-68.7892, 4.7)
  line L69 (-88.4918, 4.7) -> (-70.0107, 4.7)
  line L70 (-92.8987, 4.7) -> (-88.4918, 4.7)
  line L71 (-92.9402, 4.7) -> (-92.8987, 4.7)
  line L72 (-92.9824, 4.7) -> (-92.9402, 4.7)
  line L73 (-93.006, 4.7) -> (-92.9824, 4.7)
  line L74 (-93.0174, 4.7) -> (-93.006, 4.7)
  line L75 (-93.0229, 4.7) -> (-93.0174, 4.7)
  line L76 (-93.0272, 4.7) -> (-93.0229, 4.7)
  line L77 (-93.0304, 4.7) -> (-93.0272, 4.7)
  line L78 (-93.0304, 6.4944) -> (-93.0304, 4.7)
  line L79 (-93.0304, 6.5) -> (-93.0304, 6.4944)
  line L80 (-93.0175, 6.5) -> (-93.0304, 6.5)
  line L81 (-93.006, 6.5) -> (-93.0175, 6.5)
  line L82 (-92.9826, 6.5) -> (-93.006, 6.5)
  line L83 (-92.9405, 6.5) -> (-92.9826, 6.5)
  line L84 (-92.8992, 6.5) -> (-92.9405, 6.5)
  line L85 (-66.5663, 6.5) -> (-92.8992, 6.5)
  line L86 (-66.4877, 6.5) -> (-66.5663, 6.5)
  line L87 (-66.1088, 6.5) -> (-66.4877, 6.5)
  line L88 (-66.1088, 6.2374) -> (-66.1088, 6.5)
  line L89 (-251.1083, 4.7) -> (-251.1088, 6.2374)
  line L90 (-251.5547, 4.7) -> (-251.1083, 4.7)
  line L91 (-253.3549, 4.7) -> (-251.5547, 4.7)
  line L92 (-253.7892, 4.7) -> (-253.3549, 4.7)
  line L93 (-255.0107, 4.7) -> (-253.7892, 4.7)
  line L94 (-273.4918, 4.7) -> (-255.0107, 4.7)
  line L95 (-277.8987, 4.7) -> (-273.4918, 4.7)
  line L96 (-277.9402, 4.7) -> (-277.8987, 4.7)
  line L97 (-277.9824, 4.7) -> (-277.9402, 4.7)
  line L98 (-278.006, 4.7) -> (-277.9824, 4.7)
  line L99 (-278.0174, 4.7) -> (-278.006, 4.7)
  line L100 (-278.0229, 4.7) -> (-278.0174, 4.7)
  line L101 (-278.0272, 4.7) -> (-278.0229, 4.7)
  line L102 (-278.0304, 4.7) -> (-278.0272, 4.7)
  line L103 (-278.0304, 6.4944) -> (-278.0304, 4.7)
  line L104 (-278.0304, 6.5) -> (-278.0304, 6.4944)
  line L105 (-278.0175, 6.5) -> (-278.0304, 6.5)
  line L106 (-278.006, 6.5) -> (-278.0175, 6.5)
  line L107 (-277.9826, 6.5) -> (-278.006, 6.5)
  line L108 (-277.9405, 6.5) -> (-277.9826, 6.5)
  line L109 (-277.8992, 6.5) -> (-277.9405, 6.5)
  line L110 (-251.5663, 6.5) -> (-277.8992, 6.5)
  line L111 (-251.4877, 6.5) -> (-251.5663, 6.5)
  line L112 (-251.1088, 6.5) -> (-251.4877, 6.5)
  line L113 (-251.1088, 6.2374) -> (-251.1088, 6.5)
  line L114 (-66.1084, 10) -> (-63.3938, 10)
  line L115 (-66.1088, 8.7626) -> (-66.1084, 10)
  line L116 (-66.1088, 8.5) -> (-66.1088, 8.7626)
  line L117 (-66.4877, 8.5) -> (-66.1088, 8.5)
  line L118 (-66.5663, 8.5) -> (-66.4877, 8.5)
  line L119 (-92.8992, 8.5) -> (-66.5663, 8.5)
  line L120 (-92.9405, 8.5) -> (-92.8992, 8.5)
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extrude "Extrude138" cut sketch "Sketch47" against normal blind 5.55
extrude "Extrude139" cut of existing geometry blind -7
fillet "Fillet45" radius 3.5
sketch "Sketch48" plane through (0, 3.05, 0) normal (0, 1, 0) x axis (-1, 0, 0)
  line L1 (-251.1083, 4.7) -> (-251.1088, 6.2374)
  line L2 (-251.5547, 4.7) -> (-251.1083, 4.7)
  line L3 (-253.3549, 4.7) -> (-251.5547, 4.7)
  line L4 (-253.7892, 4.7) -> (-253.3549, 4.7)
  line L5 (-255.0107, 4.7) -> (-253.7892, 4.7)
  line L6 (-273.4918, 4.7) -> (-255.0107, 4.7)
  line L7 (-277.8987, 4.7) -> (-273.4918, 4.7)
  line L8 (-277.9402, 4.7) -> (-277.8987, 4.7)
  line L9 (-277.9824, 4.7) -> (-277.9402, 4.7)
  line L10 (-278.006, 4.7) -> (-277.9824, 4.7)
  line L11 (-278.0174, 4.7) -> (-278.006, 4.7)
  line L12 (-278.0229, 4.7) -> (-278.0174, 4.7)
  line L13 (-278.0272, 4.7) -> (-278.0229, 4.7)
  line L14 (-278.0304, 4.7) -> (-278.0272, 4.7)
  line L15 (-278.0304, 6.4944) -> (-278.0304, 4.7)
  line L16 (-278.0304, 6.5) -> (-278.0304, 6.4944)
  line L17 (-278.0175, 6.5) -> (-278.0304, 6.5)
  line L18 (-278.006, 6.5) -> (-278.0175, 6.5)
  line L19 (-277.9826, 6.5) -> (-278.006, 6.5)
  line L20 (-277.9405, 6.5) -> (-277.9826, 6.5)
  line L21 (-277.8992, 6.5) -> (-277.9405, 6.5)
  line L22 (-251.5663, 6.5) -> (-277.8992, 6.5)
  line L23 (-251.4877, 6.5) -> (-251.5663, 6.5)
  line L24 (-251.1088, 6.5) -> (-251.4877, 6.5)
  line L25 (-251.1088, 6.2374) -> (-251.1088, 6.5)
  line L26 (-66.1083, 4.7) -> (-66.1088, 6.2374)
  line L27 (-66.5547, 4.7) -> (-66.1083, 4.7)
  line L28 (-68.3549, 4.7) -> (-66.5547, 4.7)
  line L29 (-68.7892, 4.7) -> (-68.3549, 4.7)
  line L30 (-70.0107, 4.7) -> (-68.7892, 4.7)
  line L31 (-88.4918, 4.7) -> (-70.0107, 4.7)
  line L32 (-92.8987, 4.7) -> (-88.4918, 4.7)
  line L33 (-92.9402, 4.7) -> (-92.8987, 4.7)
  line L34 (-92.9824, 4.7) -> (-92.9402, 4.7)
  line L35 (-93.006, 4.7) -> (-92.9824, 4.7)
  line L36 (-93.0174, 4.7) -> (-93.006, 4.7)
  line L37 (-93.0229, 4.7) -> (-93.0174, 4.7)
  line L38 (-93.0272, 4.7) -> (-93.0229, 4.7)
  line L39 (-93.0304, 4.7) -> (-93.0272, 4.7)
  line L40 (-93.0304, 6.4944) -> (-93.0304, 4.7)
  line L41 (-93.0304, 6.5) -> (-93.0304, 6.4944)
  line L42 (-93.0175, 6.5) -> (-93.0304, 6.5)
  line L43 (-93.006, 6.5) -> (-93.0175, 6.5)
  line L44 (-92.9826, 6.5) -> (-93.006, 6.5)
  line L45 (-92.9405, 6.5) -> (-92.9826, 6.5)
  line L46 (-92.8992, 6.5) -> (-92.9405, 6.5)
  line L47 (-66.5663, 6.5) -> (-92.8992, 6.5)
  line L48 (-66.4877, 6.5) -> (-66.5663, 6.5)
  line L49 (-66.1088, 6.5) -> (-66.4877, 6.5)
  line L50 (-66.1088, 6.2374) -> (-66.1088, 6.5)
  line L51 (-118.5734, 6.5) -> (-118.9524, 6.5)
  line L52 (-118.4948, 6.5) -> (-118.5734, 6.5)
  line L53 (-93.1391, 6.5) -> (-118.4948, 6.5)
  line L54 (-93.1018, 6.5) -> (-93.1391, 6.5)
  line L55 (-93.0661, 6.5) -> (-93.1018, 6.5)
  line L56 (-93.047, 6.5) -> (-93.0661, 6.5)
  line L57 (-93.0382, 6.5) -> (-93.047, 6.5)
  line L58 (-93.0342, 6.5) -> (-93.0382, 6.5)
  line L59 (-93.0324, 6.5) -> (-93.0342, 6.5)
  line L60 (-93.0323, 6.5) -> (-93.0324, 6.5)
  line L61 (-93.0321, 6.5) -> (-93.0323, 6.5)
  line L62 (-93.0318, 6.5) -> (-93.0321, 6.5)
  line L63 (-93.0316, 6.5) -> (-93.0318, 6.5)
  line L64 (-93.0314, 6.5) -> (-93.0316, 6.5)
  line L65 (-93.0311, 6.5) -> (-93.0314, 6.5)
  line L66 (-93.0307, 6.5) -> (-93.0311, 6.5)
  line L67 (-93.0307, 4.7056) -> (-93.0307, 6.5)
  line L68 (-93.0307, 4.7) -> (-93.0307, 4.7056)
  line L69 (-93.0311, 4.7) -> (-93.0307, 4.7)
  line L70 (-93.0743, 4.7) -> (-93.0311, 4.7)
  line L71 (-93.1006, 4.7) -> (-93.0743, 4.7)
  line L72 (-93.1265, 4.7) -> (-93.1006, 4.7)
  line L73 (-93.1513, 4.7) -> (-93.1265, 4.7)
  line L74 (-93.1745, 4.7) -> (-93.1513, 4.7)
  line L75 (-93.1956, 4.7) -> (-93.1745, 4.7)
  line L76 (-93.3704, 4.7) -> (-93.1956, 4.7)
  line L77 (-93.6657, 4.7) -> (-93.3704, 4.7)
  line L78 (-94.1749, 4.7) -> (-93.6657, 4.7)
  line L79 (-94.9335, 4.7) -> (-94.1749, 4.7)
  line L80 (-95.8776, 4.7) -> (-94.9335, 4.7)
  line L81 (-96.7796, 4.7) -> (-95.8776, 4.7)
  line L82 (-115.0504, 4.7) -> (-96.7796, 4.7)
  line L83 (-116.2719, 4.7) -> (-115.0504, 4.7)
  line L84 (-116.7062, 4.7) -> (-116.2719, 4.7)
  line L85 (-118.5064, 4.7) -> (-116.7062, 4.7)
  line L86 (-118.9528, 4.7) -> (-118.5064, 4.7)
  line L87 (-118.9523, 6.2374) -> (-118.9528, 4.7)
  line L88 (-118.9524, 6.5) -> (-118.9523, 6.2374)
  line L89 (-185.5175, 6.5) -> (-185.5304, 6.5)
  line L90 (-185.506, 6.5) -> (-185.5175, 6.5)
  line L91 (-185.4826, 6.5) -> (-185.506, 6.5)
  line L92 (-185.4405, 6.5) -> (-185.4826, 6.5)
  line L93 (-185.3992, 6.5) -> (-185.4405, 6.5)
  line L94 (-159.0663, 6.5) -> (-185.3992, 6.5)
  line L95 (-158.9877, 6.5) -> (-159.0663, 6.5)
  line L96 (-158.6088, 6.5) -> (-158.9877, 6.5)
  line L97 (-158.6088, 6.2374) -> (-158.6088, 6.5)
  line L98 (-158.6083, 4.7) -> (-158.6088, 6.2374)
  line L99 (-159.0547, 4.7) -> (-158.6083, 4.7)
  line L100 (-160.8549, 4.7) -> (-159.0547, 4.7)
  line L101 (-161.2892, 4.7) -> (-160.8549, 4.7)
  line L102 (-162.5107, 4.7) -> (-161.2892, 4.7)
  line L103 (-180.9918, 4.7) -> (-162.5107, 4.7)
  line L104 (-185.3987, 4.7) -> (-180.9918, 4.7)
  line L105 (-185.4402, 4.7) -> (-185.3987, 4.7)
  line L106 (-185.4824, 4.7) -> (-185.4402, 4.7)
  line L107 (-185.506, 4.7) -> (-185.4824, 4.7)
  line L108 (-185.5174, 4.7) -> (-185.506, 4.7)
  line L109 (-185.5229, 4.7) -> (-185.5174, 4.7)
  line L110 (-185.5272, 4.7) -> (-185.5229, 4.7)
  line L111 (-185.5304, 4.7) -> (-185.5272, 4.7)
  line L112 (-185.5304, 6.4944) -> (-185.5304, 4.7)
  line L113 (-185.5304, 6.5) -> (-185.5304, 6.4944)
  line L114 (-158.6084, 10) -> (-157.0472, 10)
  line L115 (-158.6088, 8.7626) -> (-158.6084, 10)
  line L116 (-158.6088, 8.5) -> (-158.6088, 8.7626)
  line L117 (-158.9877, 8.5) -> (-158.6088, 8.5)
  line L118 (-159.0663, 8.5) -> (-158.9877, 8.5)
  line L119 (-185.3992, 8.5) -> (-159.0663, 8.5)
  line L120 (-185.4405, 8.5) -> (-185.3992, 8.5)
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extrude "Extrude140" cut sketch "Sketch48" against normal blind 5.55
extrude "Extrude141" cut of existing geometry blind -4
fillet "Fillet46" radius 3
fillet "Fillet47" radius 4
fillet "Fillet48" radius 0.5
sketch "Sketch49" plane through (0, 99.2, 0) normal (0, 1, 0) x axis (-1, 0, 0)
  line L1 (-279, 4) -> (-279, 12.5)
  line L2 (-5, -1) -> (-274, -1)
  line L3 (0, 12.5) -> (0, 4)
  line L4 (-25, 15) -> (-2.5, 15)
  line L5 (-26.7678, 13.2322) -> (-25, 15)
  line L6 (-226.7678, 13.2322) -> (-26.7678, 13.2322)
  line L7 (-228.5355, 15) -> (-226.7678, 13.2322)
  line L8 (-276.5, 15) -> (-228.5355, 15)
  circle C1 centre (-138.5, 8) radius 1.75
  arc A1 centre (-276.5, 12.5) radius 2.5 clockwise from (-279, 12.5) to (-276.5, 15)
  arc A2 centre (-274, 4) radius 5 clockwise from (-274, -1) to (-279, 4)
  arc A3 centre (-5, 4) radius 5 clockwise from (0, 4) to (-5, -1)
  arc A4 centre (-2.5, 12.5) radius 2.5 clockwise from (-2.5, 15) to (0, 12.5)
  circle C2 centre (-12, 8) radius 1.75
  circle C3 centre (-245.5, 8) radius 1.75
  circle C4 centre (-245.5, 8) radius 1
  circle C5 centre (-138.5, 8) radius 1
  circle C6 centre (-12, 8) radius 1
  circle C7 centre (-12, 9) radius 1
  circle C8 centre (-138.5, 9) radius 1
  circle C9 centre (-245.5, 9) radius 1
  point P24 (-12, 9)
  point P25 (-138.5, 9)
  point P26 (-245.5, 9)
  concentric C3 C4
  concentric C1 C5
  concentric C2 C6
  coincident C6 P24
  coincident C5 P25
  coincident C4 P26
  dimension "d509" diameter C4 = 2
  dimension "d510" diameter C5 = 2
  dimension "d511" diameter C6 = 2
  dimension "d512" diameter C7 = 2
  dimension "d513" diameter C8 = 2
  dimension "d514" diameter C9 = 2
extrude "Extrude142" new body sketch "Sketch49" profile of C1 C2 C3 C4 C5 C6 C7 C8 C9 along normal blind 1.5
delete_face "DeleteFace32"
delete_face "DeleteFace33"
delete_face "DeleteFace34"
delete_face "DeleteFace35"
delete_face "DeleteFace36"
delete_face "DeleteFace37"
extrude "Extrude143" cut of existing geometry blind -9
chamfer "Chamfer15" distance 0.75
sketch "Sketch50" plane through (0, -2.5, 0) normal (0, 1, 0) x axis (-1, 0, 0)
  curve K1 (-122.6212, 11.3) -> (-125.0123, 7.2063)
  line L1 (-63.7254, 11.3) -> (-122.6212, 11.3)
  curve K2 (-61.3343, 7.2063) -> (-63.7254, 11.3)
  line L2 (-34.8466, 4) -> (-57.8466, 4)
  curve K3 (-28.9678, 11.3) -> (-31.359, 7.2063)
  line L3 (-18, 11.3) -> (-28.9678, 11.3)
  line L4 (-18, 2.5) -> (-18, 11.3)
  line L5 (-7.5, 1) -> (-16.5, 1)
  line L6 (-6, 15) -> (-6, 2.5)
  line L7 (-203.25, 15) -> (-6, 15)
  line L8 (-204.75, 12) -> (-204.75, 13.5)
  line L9 (-204.75, 10.5) -> (-206.25, 10.5)
  line L10 (-204.75, 2.5) -> (-204.75, 10.5)
  line L11 (-194.25, 1) -> (-203.25, 1)
  line L12 (-192.75, 11.3) -> (-192.75, 2.5)
  line L13 (-157.3788, 11.3) -> (-192.75, 11.3)
  curve K4 (-154.9877, 7.2063) -> (-157.3788, 11.3)
  line L14 (-128.5, 4) -> (-151.5, 4)
  line L15 (-192.7, 10.5) -> (-204.75, 10.5)
  line L16 (-192.75, 10.6856) -> (-192.7, 10.5)
  line L17 (-203, 13.5) -> (-204.7, 10.5)
  line L18 (-191.4, 13.4) -> (-203, 13.5)
  line L19 (-191.4, 15) -> (-191.4, 13.4)
  arc A1 centre (-57.8466, 7.5) radius 3.5 clockwise from (-57.8466, 4) to (-61.3343, 7.2063)
  arc A2 centre (-34.8466, 7.5) radius 3.5 clockwise from (-31.359, 7.2063) to (-34.8466, 4)
  arc A3 centre (-16.5, 2.5) radius 1.5 clockwise from (-16.5, 1) to (-18, 2.5)
  arc A4 centre (-7.5, 2.5) radius 1.5 clockwise from (-6, 2.5) to (-7.5, 1)
  arc A5 centre (-203.25, 13.5) radius 1.5 clockwise from (-204.75, 13.5) to (-203.25, 15)
  arc A6 centre (-206.25, 12) radius 1.5 clockwise from (-204.75, 12) to (-206.25, 10.5)
  arc A7 centre (-203.25, 2.5) radius 1.5 clockwise from (-203.25, 1) to (-204.75, 2.5)
  arc A8 centre (-194.25, 2.5) radius 1.5 clockwise from (-192.75, 2.5) to (-194.25, 1)
  arc A9 centre (-151.5, 7.5) radius 3.5 clockwise from (-151.5, 4) to (-154.9877, 7.2063)
  arc A10 centre (-128.5, 7.5) radius 3.5 clockwise from (-125.0123, 7.2063) to (-128.5, 4)
  circle C1 centre (-198.75, 9) radius 1
  circle C2 centre (-12, 9) radius 1
  point P26 (-204.75, 10.5)
  point P42 (-204.75, 10.5)
  point P44 (-192.75, 10.6856)
  point P45 (-204.7, 10.5)
  point P48 (-191.4, 15)
  coincident P26 P42
  perpendicular L10 L15
  coincident L12 P44
  coincident L15 P45
  coincident L7 P48
  perpendicular L7 L19
delete_face "DeleteFace38"
extrude "Extrude144" cut sketch "Sketch50" profile of L7 A5 L8 A6 L9 L15 L17 L18 L19 against normal blind 7.5
extrude "Extrude145" cut of existing geometry blind -1
extrude "Extrude146" cut of existing geometry blind -5.5
extrude "Extrude147" cut of existing geometry blind -5.507
delete_face "DeleteFace39"
fillet "Fillet49" radius 0.85
extrude "Extrude148" cut of existing geometry blind -1.7
fillet "Fillet50" radius 2.85
delete_face "DeleteFace40"
delete_face "DeleteFace41"
extrude "Extrude149" add of existing geometry blind 1
extrude "Extrude150" cut of existing geometry blind -1 bodies "Side 2 (1)", "Side 2 (2)"
extrude "Extrude151" cut of existing geometry blind -1.9
delete_face "DeleteFace42"
sketch "Sketch51" plane through (0, -4, 0) normal (0, -1, 0) x axis (1, 0, 0)
  line L1 (186.7518, 12.3599) -> (202.0076, 12.4914)
  line L2 (185.8932, 13.3525) -> (185.8945, 13.2025)
  line L3 (185.9, 13.3526) -> (185.8932, 13.3525)
  line L4 (185.9, 14.15) -> (185.9, 13.3526)
  line L5 (2, 15) -> (185.05, 15)
  line L6 (0, 4) -> (0, 13)
  line L7 (274, -1) -> (5, -1)
  line L8 (279, 10.5) -> (279, 4)
  line L9 (206.3608, 10.5) -> (279, 10.5)
  arc A1 centre (202.0321, 9.6415) radius 2.85 clockwise from (202.0076, 12.4914) to (204.1965, 11.4958)
  arc A2 centre (186.7445, 13.2099) radius 0.85 clockwise from (186.7518, 12.3599) to (185.8945, 13.2025)
  arc A3 centre (185.05, 14.15) radius 0.85 clockwise from (185.05, 15) to (185.9, 14.15)
  arc A4 centre (2, 13) radius 2 clockwise from (0, 13) to (2, 15)
  arc A5 centre (5, 4) radius 5 clockwise from (5, -1) to (0, 4)
  arc A6 centre (274, 4) radius 5 clockwise from (279, 4) to (274, -1)
  arc A7 centre (206.3608, 13.35) radius 2.85 clockwise from (206.3608, 10.5) to (204.1965, 11.4958)
  circle C1 centre (12, 9) radius 1.75
  circle C2 centre (200.75, 9) radius 1
  dimension "d540" diameter C2 = 2
extrude "Extrude152" cut sketch "Sketch51" profile of C2 against normal blind 5
delete_face "DeleteFace43"
extrude "Extrude153" cut of existing geometry blind -1
extrude "Extrude154" add of existing geometry blind 1 bodies "Side 2 (2)", "Side 2 (1)"
fillet "Fillet51" radius 2.5
fillet "Fillet52" radius 1
delete_face "DeleteFace44"
extrude "Extrude155" add of existing geometry blind 0.8
delete_face "DeleteFace45"
delete_face "DeleteFace46"
delete_face "DeleteFace47"
delete_face "DeleteFace48"
delete_face "DeleteFace49"
delete_face "DeleteFace50"
extrude "Extrude156" cut of existing geometry blind -0.8
fillet "Fillet53" radius 1
delete_face "DeleteFace51"
delete_face "DeleteFace52"
delete_face "DeleteFace53"
delete_face "DeleteFace54"
delete_face "DeleteFace55"
delete_face "DeleteFace56"
extrude "Extrude157" cut of existing geometry blind -2
extrude "Extrude158" add of existing geometry blind 2
sketch "Sketch52" plane through (0, 0, 10.3) normal (0, 0, 1) x axis (-1, 0, 0)
  line L1 (-269.32, -93.3955) -> (-255.1337, -91.3393)
  line L2 (-251.7589, -94.714) -> (-269.32, -93.3955)
  line L3 (-255.1337, -91.3393) -> (-251.7589, -94.714)
  line L4 (-251.175, -95) -> (-253.5, -95)
  line L5 (-251.175, -92.814) -> (-251.175, -95)
  line L6 (-253.5, -92.814) -> (-251.175, -92.814)
  line L7 (-253.5, -95) -> (-253.5, -92.814)
  horizontal L4
  vertical L5
  horizontal L6
  vertical L7
extrude "Extrude159" cut sketch "Sketch52" profile of L2 L3 L4 L5 L6 L7 against normal blind 6.5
